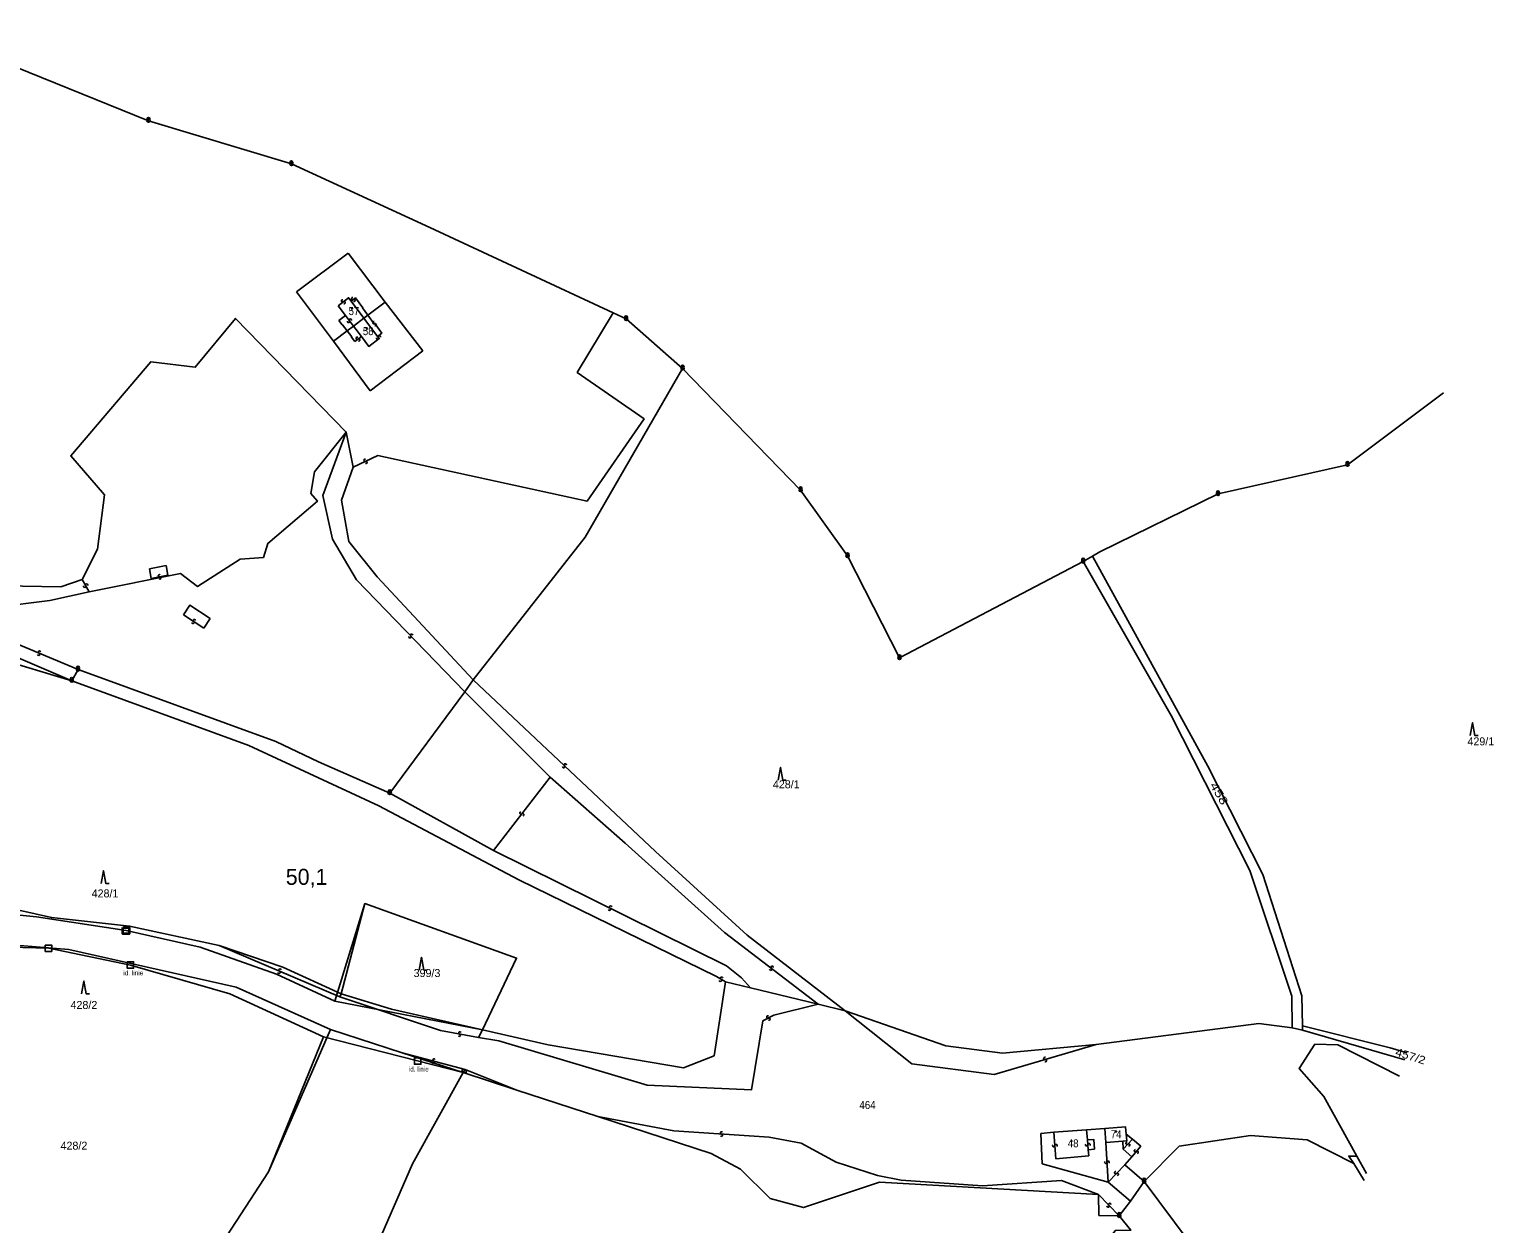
# Model space of a CAD drawing. Extents: x -680102 to -677253, y -1007548 to -1006096.
# Drawn here: x -677710.2 to -677252.6, y -1006469.8 to -1006096.5 of the extents above; entities that cross this region are included whole.
import ezdxf
from ezdxf.enums import TextEntityAlignment as Align

# ---------------------------------------------------------------- set-up
doc = ezdxf.new("R2010")
doc.units = 0
for name, color, linetype, lineweight in [('1', 7, 'Continuous', 25), ('11', 7, 'Continuous', 25), ('13', 7, 'Continuous', 25), ('24', 7, 'Continuous', 25), ('25', 7, 'Continuous', 25), ('35', 7, 'Continuous', 25), ('4', 7, 'Continuous', 25)]:
    doc.layers.add(name, color=color, linetype=linetype, lineweight=lineweight)
for name, color, linetype in [('18', 7, 'Continuous'), ('19', 7, 'Continuous'), ('56', 7, 'Continuous')]:
    doc.layers.add(name, color=color, linetype=linetype)

msp = doc.modelspace()

# ---------------------------------------------------------------- linework, layer by layer
at = {"layer": '1'}
for p, q in [((-677610.54, -1006166.43), (-677626.75, -1006178.58)), ((-677599.02, -1006181.8), (-677610.54, -1006166.43)), ((-677626.75, -1006178.58), (-677615.14, -1006193.94)), ((-677599.02, -1006181.8), (-677604.41, -1006185.86)), ((-677587.27, -1006196.99), (-677599.02, -1006181.8)), ((-677608.9, -1006189.24), (-677610.88, -1006190.74)), ((-677610.88, -1006190.74), (-677615.14, -1006193.94)), ((-677615.14, -1006193.94), (-677603.67, -1006209.47)), ((-677587.27, -1006196.99), (-677603.67, -1006209.47)), ((-677378.02, -1006261.14), (-677341.98, -1006326.73)), ((-677729.71, -1006290.21), (-677696.92, -1006300.06)), ((-677696.92, -1006300.06), (-677694.97, -1006296.56)), ((-677694.97, -1006296.56), (-677633.15, -1006319.04)), ((-677574.06, -1006303.56), (-677571.46, -1006299.81)), ((-677633.15, -1006319.04), (-677619.87, -1006325.42)), ((-677328.81, -1006359.33), (-677315.75, -1006398.65)), ((-677315.75, -1006398.65), (-677315.59, -1006408.51)), ((-677463.66, -1006401.16), (-677455.24, -1006403.19)), ((-677455.24, -1006403.19), (-677423.8, -1006414.14)), ((-677376.88, -1006413.74), (-677326.06, -1006407.21)), ((-677326.06, -1006407.21), (-677315.59, -1006408.51)), ((-677315.59, -1006408.51), (-677312.36, -1006409.27)), ((-677284.96, -1006414.78), (-677312.39, -1006407.96)), ((-677312.36, -1006409.27), (-677280.37, -1006418.6)), ((-677423.8, -1006414.14), (-677406.09, -1006416.48)), ((-677406.09, -1006416.48), (-677376.88, -1006413.74)), ((-677279.61, -1006416.37), (-677284.96, -1006414.78)), ((-677574.61, -1006422.53), (-677590.47, -1006451.07)), ((-677574.61, -1006422.53), (-677557.88, -1006428)), ((-677390.08, -1006441.2), (-677394.17, -1006441.55)), ((-677393.69, -1006451.1), (-677394.17, -1006441.55)), ((-677390.08, -1006441.2), (-677379.82, -1006440.39)), ((-677379.82, -1006440.39), (-677374.18, -1006440.03)), ((-677368.51, -1006443.99), (-677368.38, -1006446.46)), ((-677368.38, -1006446.46), (-677365.72, -1006448.84)), ((-677590.47, -1006451.07), (-677605.94, -1006486.49)), ((-677373.08, -1006456.73), (-677393.69, -1006451.1)), ((-677365.72, -1006448.84), (-677367.88, -1006451.39)), ((-677296.33, -1006450.99), (-677293.11, -1006456.21)), ((-677366.15, -1006462.76), (-677373.08, -1006456.73)), ((-677366.15, -1006462.76), (-677369.62, -1006467.29))]:
    msp.add_line(p, q, dxfattribs=at)
for points in [[(-677604.41, -1006185.86), (-677605.63, -1006186.78), (-677608.9, -1006189.24)], [(-677571.46, -1006299.81), (-677536.53, -1006255.19), (-677506.05, -1006202.45)], [(-677380.89, -1006262.82), (-677353.45, -1006310.95), (-677328.81, -1006359.33)], [(-677619.87, -1006325.42), (-677597.56, -1006335.17), (-677574.06, -1006303.56)], [(-677312.61, -1006398.55), (-677324.71, -1006360.65), (-677341.98, -1006326.73)], [(-677770.39, -1006346.95), (-677718.61, -1006370.68), (-677703.31, -1006374.09), (-677678.84, -1006376.76), (-677650.86, -1006382.82), (-677630.98, -1006389.59), (-677612.71, -1006397.93), (-677596.98, -1006402.74)], [(-677568.61, -1006409.18), (-677557.92, -1006386.74), (-677605.33, -1006369.72), (-677612.71, -1006397.93)], [(-677710.93, -1006508.5), (-677682.78, -1006511.05), (-677659.9, -1006491.14), (-677635.46, -1006453.54), (-677616.1, -1006409.05), (-677645.51, -1006395.86), (-677697.86, -1006384.12), (-677718.21, -1006382.38), (-677754.71, -1006390.36), (-677769.19, -1006389.6)], [(-677548.06, -1006413.85), (-677505.74, -1006421.01), (-677496.22, -1006417.27), (-677492.65, -1006394.17)], [(-677492.65, -1006394.17), (-677484.89, -1006396.04), (-677463.66, -1006401.16)], [(-677312.36, -1006409.27), (-677312.39, -1006407.96), (-677312.61, -1006398.55)], [(-677596.98, -1006402.74), (-677568.61, -1006409.18), (-677548.06, -1006413.85)], [(-677616.1, -1006409.05), (-677593.66, -1006416.34), (-677574.61, -1006422.53)], [(-677557.88, -1006428), (-677532.59, -1006436.26), (-677497.11, -1006447.85)], [(-677374.18, -1006440.03), (-677367.65, -1006439.52), (-677367.46, -1006441.82)], [(-677374.18, -1006440.03), (-677373.84, -1006444.36), (-677368.51, -1006443.99)], [(-677367.46, -1006441.82), (-677367.29, -1006443.91), (-677368.51, -1006443.99)], [(-677350.94, -1006445.48), (-677328.66, -1006442.17), (-677310.9, -1006443.59)], [(-677342.85, -1006482.04), (-677361.85, -1006456.57), (-677350.94, -1006445.48)], [(-677310.9, -1006443.59), (-677296.33, -1006450.99), (-677297.92, -1006448.63), (-677295.39, -1006448.69)], [(-677497.11, -1006447.85), (-677488.02, -1006452.74), (-677478.69, -1006461.9), (-677468.33, -1006464.73), (-677444.49, -1006456.8), (-677376.1, -1006460.68), (-677375.96, -1006467.15), (-677369.62, -1006467.29), (-677365.98, -1006471.74), (-677370.84, -1006471.88), (-677428.55, -1006540.9), (-677449.44, -1006576.04)], [(-677367.88, -1006451.39), (-677361.85, -1006456.57), (-677366.15, -1006462.76)]]:
    msp.add_lwpolyline(points, dxfattribs=at)
at = {"layer": '11'}
for p, q in [((-677614.75, -1006400.23), (-677605.33, -1006369.72)), ((-677720.56, -1006383.26), (-677704.12, -1006383.69)), ((-677704.12, -1006383.69), (-677678.6, -1006388.92)), ((-677656.86, -1006383.31), (-677632.95, -1006391.74)), ((-677678.6, -1006388.92), (-677647.54, -1006397.88)), ((-677632.95, -1006391.74), (-677614.75, -1006400.23)), ((-677647.54, -1006397.88), (-677618.24, -1006411.32)), ((-677614.75, -1006400.23), (-677568.61, -1006409.18)), ((-677618.24, -1006411.32), (-677635.46, -1006453.54)), ((-677618.24, -1006411.32), (-677574.61, -1006422.53))]:
    msp.add_line(p, q, dxfattribs=at)
msp.add_lwpolyline([(-677719.47, -1006372.74), (-677707.93, -1006373.88), (-677679.98, -1006378.16), (-677656.86, -1006383.31)], dxfattribs=at)
at = {"layer": '13'}
for p, q in [((-677527.75, -1006185.14), (-677523.72, -1006187.02)), ((-677523.72, -1006187.02), (-677506.05, -1006202.45)), ((-677268.27, -1006210.13), (-677298.33, -1006232.57)), ((-677301.3, -1006413.85), (-677308.53, -1006413.63)), ((-677301.3, -1006413.85), (-677282.1, -1006423.7)), ((-677292.4, -1006454.11), (-677295.39, -1006448.69))]:
    msp.add_line(p, q, dxfattribs=at)
for points in [[(-677527.75, -1006185.14), (-677585.01, -1006158.46), (-677628.3, -1006138.59), (-677672.94, -1006125.05), (-677743.77, -1006096.49)], [(-677380.89, -1006262.82), (-677438.28, -1006292.95), (-677454.52, -1006261.07), (-677469.19, -1006240.48), (-677506.05, -1006202.45)], [(-677298.33, -1006232.57), (-677338.76, -1006241.7), (-677375.7, -1006259.78)], [(-677380.89, -1006262.82), (-677378.02, -1006261.14), (-677375.7, -1006259.78)], [(-677308.53, -1006413.63), (-677313.45, -1006421.29), (-677305.68, -1006430.06), (-677295.39, -1006448.69)]]:
    msp.add_lwpolyline(points, dxfattribs=at)
at = {"layer": '24'}
for centre, radius in [((-677672.94, -1006125.05), 0.5), ((-677672.94, -1006125.05), 0.022), ((-677628.3, -1006138.59), 0.5), ((-677628.3, -1006138.59), 0.022), ((-677523.72, -1006187.02), 0.5), ((-677523.72, -1006187.02), 0.022), ((-677506.05, -1006202.45), 0.5), ((-677506.05, -1006202.45), 0.022), ((-677298.33, -1006232.57), 0.5), ((-677298.33, -1006232.57), 0.022), ((-677469.19, -1006240.48), 0.5), ((-677469.19, -1006240.48), 0.022), ((-677338.76, -1006241.7), 0.5), ((-677338.76, -1006241.7), 0.022), ((-677454.52, -1006261.07), 0.5), ((-677454.52, -1006261.07), 0.022), ((-677380.89, -1006262.82), 0.5), ((-677380.89, -1006262.82), 0.022), ((-677438.28, -1006292.95), 0.5), ((-677438.28, -1006292.95), 0.022), ((-677696.92, -1006300.06), 0.5), ((-677696.92, -1006300.06), 0.022), ((-677694.97, -1006296.56), 0.5), ((-677694.97, -1006296.56), 0.022), ((-677597.56, -1006335.17), 0.5), ((-677597.56, -1006335.17), 0.022), ((-677361.85, -1006456.57), 0.5), ((-677361.85, -1006456.57), 0.022), ((-677369.62, -1006467.29), 0.5), ((-677369.62, -1006467.29), 0.022)]:
    msp.add_circle(centre, radius, dxfattribs=at)
for centre in [(-677672.941, -1006124.487), (-677628.301, -1006138.027), (-677523.721, -1006186.457), (-677506.051, -1006201.887), (-677298.331, -1006232.007), (-677469.191, -1006239.917), (-677338.761, -1006241.137), (-677454.521, -1006260.507), (-677380.891, -1006262.257), (-677694.971, -1006295.997), (-677438.281, -1006292.387), (-677696.921, -1006299.497), (-677597.561, -1006334.607), (-677361.851, -1006456.007), (-677369.621, -1006466.727)]:
    msp.add_arc(centre, 0.437, 328.35109, 209.97456, dxfattribs=at)
at = {"layer": '25'}
for points in [[(-677259.97, -1006317.23), (-677259.22, -1006313.23), (-677258.47, -1006317.23), (-677257.47, -1006317.23)], [(-677476.21, -1006331.18), (-677475.46, -1006327.18), (-677474.71, -1006331.18), (-677473.71, -1006331.18)], [(-677687.78, -1006363.45), (-677687.03, -1006359.45), (-677686.28, -1006363.45), (-677685.28, -1006363.45)], [(-677588.4, -1006390.49), (-677587.65, -1006386.49), (-677586.9, -1006390.49), (-677585.9, -1006390.49)], [(-677693.9, -1006397.95), (-677693.15, -1006393.95), (-677692.4, -1006397.95), (-677691.4, -1006397.95)]]:
    msp.add_lwpolyline(points, dxfattribs=at)
for centre in [(-677609.35, -1006183.74), (-677604.74, -1006190.07), (-677370.64, -1006440.93), (-677384.55, -1006443.89)]:
    msp.add_circle(centre, 0.175, dxfattribs=at)
for centre, radius, start, end in [((-677612.279, -1006181.345), 0.367, 74.38593, 306.59163), ((-677609.199, -1006180.645), 0.367, 74.38593, 306.59163), ((-677608.762, -1006181.237), 0.369, 254.27002, 126.55739), ((-677611.842, -1006181.937), 0.369, 254.27002, 126.55739), ((-677610.445, -1006187.809), 0.367, 164.43397, 36.58948), ((-677609.853, -1006187.372), 0.369, 344.27073, 216.50874), ((-677602.558, -1006188.194), 0.368, 73.95394, 306.37358), ((-677602.123, -1006188.787), 0.368, 254.27002, 126.43221), ((-677607.688, -1006193.013), 0.369, 74.41823, 306.28136), ((-677607.251, -1006193.605), 0.368, 253.95693, 126.5902), ((-677601.397, -1006193.007), 0.368, 164.2693, 36.15651), ((-677600.804, -1006192.572), 0.368, 343.86434, 216.37286), ((-677605.3, -1006231.184), 0.368, 61.82352, 294.05969), ((-677605, -1006231.857), 0.369, 241.83801, 113.98793), ((-677669.545, -1006267.248), 0.368, 47.98958, 280.18167), ((-677669.416, -1006267.973), 0.368, 228.08399, 99.92596), ((-677692.902, -1006270.559), 0.369, 157.04716, 28.79366), ((-677692.259, -1006270.2), 0.368, 336.88263, 209.28309), ((-677659.032, -1006281.867), 0.368, 184.13815, 56.65632), ((-677658.626, -1006281.253), 0.369, 4.19628, 236.25738), ((-677591.266, -1006286.334), 0.368, 171.44231, 43.67837), ((-677590.732, -1006285.827), 0.369, 351.41046, 223.62218), ((-677706.994, -1006291.142), 0.368, 14.7912, 246.852), ((-677707.284, -1006291.818), 0.367, 194.96727, 66.92481), ((-677543.225, -1006326.916), 0.369, 173.9355, 45.95051), ((-677542.716, -1006326.384), 0.368, 353.77302, 226.32377), ((-677556.589, -1006341.452), 0.369, 89.69017, 321.61054), ((-677556.011, -1006341.907), 0.367, 269.26837, 141.85266), ((-677528.897, -1006371.498), 0.368, 191.09823, 63.02062), ((-677528.564, -1006370.842), 0.368, 11.00215, 243.15807), ((-677632.167, -1006391.176), 0.367, 193.97796, 66.37115), ((-677631.871, -1006390.503), 0.369, 14.30039, 246.36351), ((-677478.536, -1006390.23), 0.368, 179.69486, 52.07076), ((-677478.082, -1006389.651), 0.369, 359.84759, 231.86424), ((-677494.257, -1006393.666), 0.367, 186.98273, 59.38461), ((-677493.881, -1006393.034), 0.369, 7.16361, 239.19987), ((-677479.419, -1006405.158), 0.368, 63.92218, 295.59429), ((-677479.099, -1006405.82), 0.367, 243.54341, 116.00769), ((-677575.668, -1006410.149), 0.368, 26.77386, 258.89198), ((-677575.81, -1006410.871), 0.367, 206.63099, 79.02683), ((-677583.928, -1006419.295), 0.368, 202.66932, 74.57095), ((-677583.733, -1006418.585), 0.368, 22.4598, 254.7196), ((-677392.89, -1006418.105), 0.368, 53.84708, 285.73428), ((-677392.689, -1006418.813), 0.368, 233.60571, 105.96767), ((-677574.624, -1006421.838), 0.368, 96.59403, 328.55829), ((-677573.996, -1006422.223), 0.368, 276.39393, 148.57699), ((-677493.863, -1006441.373), 0.368, 33.63306, 265.79447), ((-677493.919, -1006442.107), 0.368, 213.8212, 85.72704), ((-677390.097, -1006445.366), 0.368, 132.03444, 3.79564), ((-677389.364, -1006445.313), 0.367, 311.65991, 184.22056), ((-677379.818, -1006445.135), 0.369, 131.81513, 3.52513), ((-677379.084, -1006445.084), 0.367, 311.67413, 184.06483), ((-677367.198, -1006444.627), 0.369, 84.70772, 316.65165), ((-677366.661, -1006445.131), 0.368, 264.67102, 136.98361), ((-677364.577, -1006446.948), 0.368, 86.90918, 318.86057), ((-677373.827, -1006450.57), 0.367, 130.93138, 3.11933), ((-677373.092, -1006450.532), 0.369, 311.04216, 183.17116), ((-677364.023, -1006447.434), 0.369, 266.42578, 138.73523), ((-677370.741, -1006453.8), 0.368, 82.99128, 314.75687), ((-677370.218, -1006454.318), 0.368, 262.9438, 135.44181), ((-677373.126, -1006464.245), 0.369, 171.58578, 43.52757), ((-677372.595, -1006463.735), 0.368, 351.7583, 223.90008)]:
    msp.add_arc(centre, radius, start, end, dxfattribs=at)
at = {"layer": '35', "lineweight": 35}
msp.add_lwpolyline([(-677680.98, -1006377.16), (-677678.98, -1006377.16), (-677678.98, -1006379.16), (-677680.98, -1006379.16)], close=True, dxfattribs=at)
at = {"layer": '35'}
for points in [[(-677705.19, -1006382.68), (-677703.19, -1006382.68), (-677703.19, -1006384.68), (-677705.19, -1006384.68)], [(-677679.6, -1006387.92), (-677677.6, -1006387.92), (-677677.6, -1006389.92), (-677679.6, -1006389.92)], [(-677589.84, -1006417.94), (-677587.84, -1006417.94), (-677587.84, -1006419.94), (-677589.84, -1006419.94)]]:
    msp.add_lwpolyline(points, close=True, dxfattribs=at)
at = {"layer": '4'}
for p, q in [((-677672.63, -1006265.14), (-677672.09, -1006268.1)), ((-677672.09, -1006268.1), (-677666.87, -1006267.12)), ((-677655.63, -1006283.64), (-677662.04, -1006279.49)), ((-677653.71, -1006280.63), (-677655.63, -1006283.64)), ((-677733.39, -1006284.58), (-677696.92, -1006300.06)), ((-677547.46, -1006330.2), (-677574.06, -1006303.56)), ((-677565.13, -1006353.16), (-677597.56, -1006335.17)), ((-677613.17, -1006398.85), (-677650.86, -1006382.82)), ((-677593.66, -1006416.34), (-677574.01, -1006421.53)), ((-677532.59, -1006436.26), (-677508.8, -1006440.75)), ((-677367.46, -1006441.82), (-677365.47, -1006443.3)), ((-677379.33, -1006446.63), (-677379.18, -1006448.54)), ((-677373.08, -1006456.73), (-677373.84, -1006444.36)), ((-677365.47, -1006443.3), (-677368.38, -1006446.46)), ((-677365.72, -1006448.84), (-677362.88, -1006445.54)), ((-677362.88, -1006445.54), (-677365.47, -1006443.3)), ((-677367.88, -1006451.39), (-677373.08, -1006456.73))]:
    msp.add_line(p, q, dxfattribs=at)
for points in [[(-677613.69, -1006182.87), (-677610.42, -1006180.41), (-677609.65, -1006181.44), (-677608.31, -1006180.43), (-677606.01, -1006183.49), (-677606.13, -1006183.58)], [(-677613.69, -1006182.87), (-677611.39, -1006185.93), (-677613.47, -1006187.5)], [(-677606.43, -1006192.52), (-677608.9, -1006189.24), (-677611.39, -1006185.93)], [(-677601.36, -1006192.45), (-677605.63, -1006186.78), (-677609.65, -1006181.44)], [(-677609.04, -1006233.3), (-677601.25, -1006229.73), (-677535.89, -1006243.98), (-677518.1, -1006218.27), (-677538.98, -1006203.7), (-677527.75, -1006185.14)], [(-677606.13, -1006183.58), (-677604.41, -1006185.86), (-677602.4, -1006188.53)], [(-677694.97, -1006296.56), (-677719.3, -1006286.4), (-677720.42, -1006277.08), (-677703.77, -1006275), (-677691.48, -1006272.31), (-677662.94, -1006266.54), (-677657.67, -1006270.6), (-677644.27, -1006262.08), (-677637.04, -1006261.52), (-677635.64, -1006257.17), (-677620.16, -1006244.01), (-677622.25, -1006241.57), (-677621.08, -1006234.8), (-677611.17, -1006222.35), (-677645.8, -1006186.87), (-677658.37, -1006202.13), (-677672.27, -1006200.39), (-677697.23, -1006229.81), (-677686.75, -1006242), (-677688.84, -1006258.97), (-677693.69, -1006268.44), (-677691.48, -1006272.31)], [(-677612.32, -1006188.82), (-677612.42, -1006188.89), (-677613.47, -1006187.5)], [(-677609.45, -1006192.65), (-677610.88, -1006190.74), (-677612.32, -1006188.82)], [(-677602.4, -1006188.53), (-677602.28, -1006188.44), (-677600.02, -1006191.45), (-677601.36, -1006192.45), (-677600.85, -1006193.13), (-677604.12, -1006195.59), (-677606.43, -1006192.52), (-677608.51, -1006194.09)], [(-677608.51, -1006194.09), (-677609.54, -1006192.72), (-677609.45, -1006192.65)], [(-677574.06, -1006303.56), (-677607.94, -1006268.59), (-677615.5, -1006255.84), (-677618.5, -1006242.22), (-677611.17, -1006222.35), (-677609.04, -1006233.3), (-677612.62, -1006243.66), (-677610.36, -1006256.57), (-677601.5, -1006267.63), (-677571.46, -1006299.81)], [(-677693.69, -1006268.44), (-677700.34, -1006270.73), (-677724.43, -1006270.32), (-677755.14, -1006267.99), (-677743.77, -1006275.31), (-677733.79, -1006280.23)], [(-677666.87, -1006267.12), (-677667.44, -1006264.09), (-677672.63, -1006265.14)], [(-677662.04, -1006279.49), (-677660.05, -1006276.47), (-677653.71, -1006280.63)], [(-677492.65, -1006394.17), (-677495.49, -1006392.52), (-677557.19, -1006362.28), (-677600.93, -1006339.15), (-677641.62, -1006320.29), (-677696.92, -1006300.06)], [(-677571.46, -1006299.81), (-677514.49, -1006353.49), (-677485.86, -1006379.54), (-677455.24, -1006403.19)], [(-677477.55, -1006404.64), (-677463.66, -1006401.16), (-677492.96, -1006378.72), (-677524.03, -1006350.89), (-677547.46, -1006330.2), (-677565.13, -1006353.16)], [(-677565.13, -1006353.16), (-677492.34, -1006389.17), (-677487.67, -1006392.93), (-677484.89, -1006396.04)], [(-677569.8, -1006411.62), (-677581.68, -1006409.4), (-677613.17, -1006398.85), (-677612.71, -1006397.93)], [(-677477.55, -1006404.64), (-677480.96, -1006406.34), (-677484.51, -1006427.89), (-677517.11, -1006426.43), (-677563.47, -1006412.66), (-677569.8, -1006411.62), (-677568.61, -1006409.18)], [(-677376.88, -1006413.74), (-677408.7, -1006423.18), (-677434.41, -1006419.76), (-677455.24, -1006403.19)], [(-677574.61, -1006422.53), (-677574.01, -1006421.53), (-677557.88, -1006428)], [(-677508.8, -1006440.75), (-677478.98, -1006442.72), (-677469.01, -1006444.59), (-677458.1, -1006450.52), (-677445.13, -1006454.67), (-677437.77, -1006456.13), (-677412.31, -1006457.9), (-677387.69, -1006456.23), (-677376.1, -1006460.68), (-677369.62, -1006467.29)], [(-677390.08, -1006441.2), (-677389.39, -1006449.48), (-677379.18, -1006448.54)], [(-677379.82, -1006440.39), (-677379.57, -1006443.58), (-677379.33, -1006446.63), (-677377.34, -1006446.46)], [(-677379.57, -1006443.58), (-677377.58, -1006443.43), (-677377.34, -1006446.46)]]:
    msp.add_lwpolyline(points, dxfattribs=at)

# ---------------------------------------------------------------- texts
at = {"layer": '18'}
for s, p in [('429/1', (-677260.82, -1006320.27)), ('428/1', (-677477.85, -1006333.7)), ('428/1', (-677690.72, -1006367.79)), ('399/3', (-677590.11, -1006392.68)), ('428/2', (-677697.32, -1006402.65)), ('428/2', (-677700.44, -1006446.63))]:
    msp.add_text(s, height=2.5, dxfattribs=at).set_placement(p)
for s, rotation, width, p in [('458', 300.602, 1.35, (-677341.427, -1006332.71)), ('457/2', 342.703, 1.15, (-677283.57, -1006417.169))]:
    msp.add_text(s, height=2.5, rotation=rotation, dxfattribs=dict(at, width=width)).set_placement(p)
at = {"layer": '18', "width": 0.9}
msp.add_text('464', height=2.5, dxfattribs=at).set_placement((-677450.8, -1006433.92))
at = {"layer": '19', "width": 0.9}
for s, p in [('57', (-677610.43, -1006185.8)), ('58', (-677605.98, -1006192.07)), ('48', (-677385.7, -1006445.88))]:
    msp.add_text(s, height=2.5, dxfattribs=at).set_placement(p)
msp.add_text('74', height=2.5, dxfattribs=at).set_placement((-677370.6, -1006443.05), align=Align.CENTER)
at = {"layer": '35', "width": 0.8}
for p in [(-677680.83, -1006392.13), (-677591.61, -1006422.2)]:
    msp.add_text('id. linie', height=1.5, dxfattribs=at).set_placement(p)
at = {"layer": '56'}
msp.add_text('50,1', height=5, dxfattribs=at).set_placement((-677630.06, -1006363.86))

doc.saveas('drawing.dxf')
